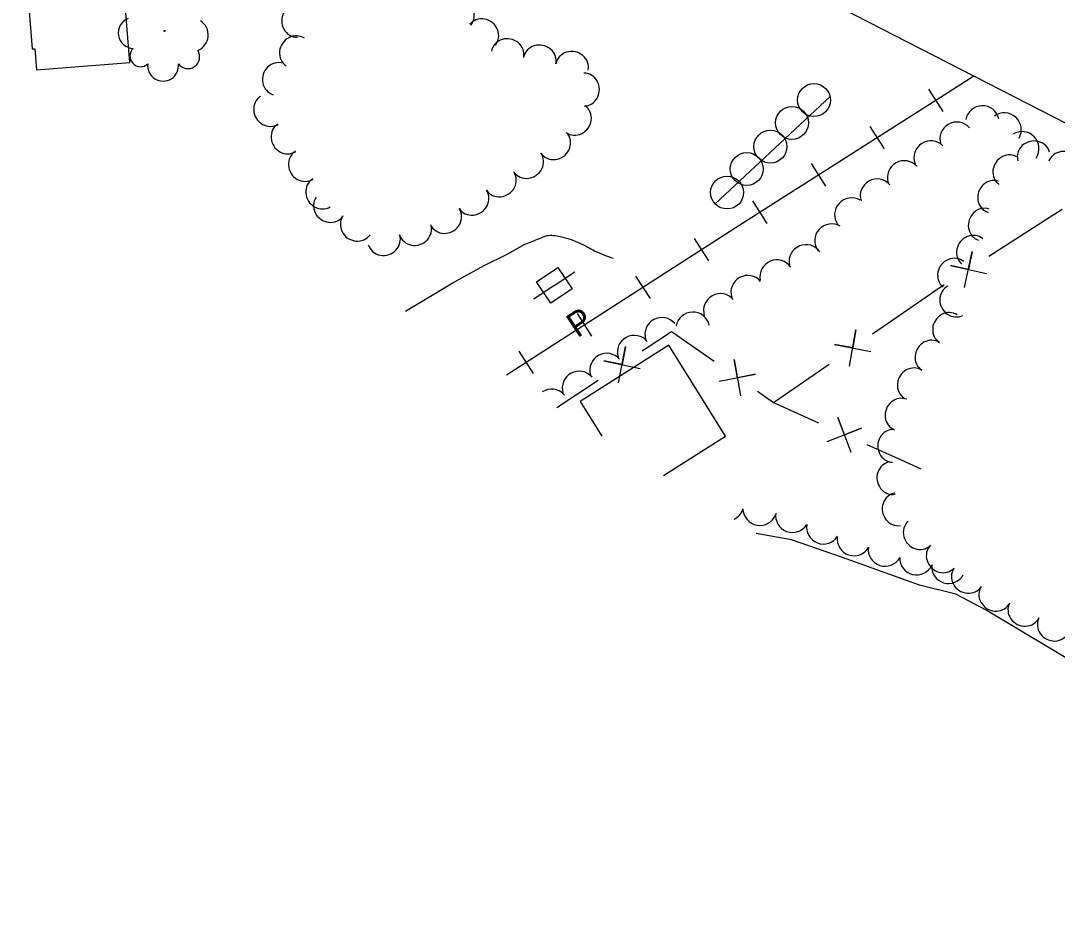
# Model space of a CAD drawing. Extents: x 1746010 to 1754829, y 655801 to 663091.
# Drawn here: x 1746597.6 to 1746912.4, y 662299.8 to 662573.6 of the extents above; entities that cross this region are included whole.
import ezdxf

# ---------------------------------------------------------------- set-up
doc = ezdxf.new("R2010")
doc.units = 0
for name, color, linetype in [('SURVEY - AERIAL SURVEY - Photo Control - Points - Elevations', 7, 'Continuous'), ('SURVEY - AERIAL SURVEY - Photo Control - Points - Locators', 7, 'Continuous'), ('SURVEY - AERIAL SURVEY - Photo Control with Text', 7, 'Continuous'), ('SURVEY - CENTERLINE - Existing Roads - Development', 7, 'Continuous'), ('SURVEY - CENTERLINE - Existing Roads Curve Text', 7, 'Continuous'), ('SURVEY - CENTERLINE - Existing Roads Text', 7, 'Continuous')]:
    doc.layers.add(name, color=color, linetype=linetype)

msp = doc.modelspace()

# ---------------------------------------------------------------- linework, layer by layer
at = {"layer": 'SURVEY - AERIAL SURVEY - Photo Control - Points - Elevations'}
msp.add_lwpolyline([(1746939.36, 662658.3), (1747047.15, 662601.95), (1746935.67, 662531.86), (1746826.79, 662587.8)], dxfattribs=at)
at = {"layer": 'SURVEY - AERIAL SURVEY - Photo Control - Points - Locators'}
for p, q in [((1746877.74, 662546.04), (1746873.38, 662552.86)), ((1746859.93, 662534.72), (1746855.57, 662541.54)), ((1746842.12, 662523.4), (1746837.77, 662530.22)), ((1746824.32, 662512.08), (1746819.96, 662518.9)), ((1746806.57, 662500.69), (1746802.18, 662507.5)), ((1746788.82, 662489.27), (1746784.44, 662496.08)), ((1746771.08, 662477.86), (1746766.69, 662484.66)), ((1746753.33, 662466.44), (1746748.95, 662473.25))]:
    msp.add_line(p, q, dxfattribs=at)
for points in [[(1746887.11, 662556.81), (1746879.12, 662551.72), (1746817.44, 662512.5), (1746745.08, 662465.95)], [(1746714.45, 662485.44), (1746728.61, 662493.92), (1746738.34, 662499.27), (1746745.47, 662502.86), (1746750.71, 662505.8)], [(1747021.09, 662299.79), (1747018.78, 662306.1), (1747009.96, 662317.06), (1746994.58, 662331.26), (1746981.41, 662340.35), (1746952.61, 662356.87), (1746930.16, 662371.03), (1746910.96, 662382.58), (1746890.81, 662394.58), (1746881.63, 662399.49), (1746870.54, 662402.23), (1746847.21, 662410.58), (1746831.64, 662415.93), (1746820.94, 662417.91)]]:
    msp.add_lwpolyline(points, dxfattribs=at)
msp.add_spline([(1746750.71, 662505.8), (1746755.1, 662507.49), (1746757.41, 662508.35), (1746761.43, 662508.07), (1746767.41, 662506.09), (1746771.87, 662503.74), (1746777.48, 662501.47)], degree=3, dxfattribs=at)
at = {"layer": 'SURVEY - AERIAL SURVEY - Photo Control with Text'}
for p, q in [((1746808.36, 662517.96), (1746843.47, 662550.64)), ((1746838.52, 662549.5), (1746838.52, 662549.5)), ((1746831.87, 662542.6), (1746831.87, 662542.6)), ((1746825.31, 662535.39), (1746825.31, 662535.39)), ((1746818.14, 662528.6), (1746818.14, 662528.6)), ((1746812.16, 662521.45), (1746812.16, 662521.45))]:
    msp.add_line(p, q, dxfattribs=at)
for centre in [(1746838.51, 662549.54), (1746831.83, 662542.6), (1746825.27, 662535.39), (1746818.1, 662528.6), (1746812.12, 662521.45)]:
    msp.add_circle(centre, 5, dxfattribs=at)
at = {"layer": 'SURVEY - CENTERLINE - Existing Roads - Development'}
for points in [[(1746602.38, 662558.69), (1746630.75, 662560.99), (1746627.8, 662597.33), (1746622.54, 662602.85), (1746608.66, 662601.72), (1746608.07, 662609.06), (1746597.57, 662608.21), (1746601.07, 662565.09), (1746601.86, 662565.15), (1746602.38, 662558.69)], [(1746901.24, 662508.29), (1746913.89, 662516.36)], [(1746891.63, 662502.15), (1746901.24, 662508.29)], [(1746884.23, 662492.56), (1746886.58, 662503.56), (1746885.45, 662498.09), (1746879.93, 662499.31), (1746890.89, 662496.81)], [(1746865.67, 662485.04), (1746875.48, 662491.84), (1746878.06, 662493.49)], [(1746856.3, 662478.54), (1746865.67, 662485.04)], [(1746786.34, 662473.35), (1746795.21, 662479.23), (1746795.83, 662478.8)], [(1746849.27, 662468.67), (1746851.2, 662479.75), (1746850.28, 662474.24), (1746844.71, 662475.25), (1746855.76, 662473.18)], [(1746795.83, 662478.8), (1746808.15, 662470.25)], [(1746779.1, 662463.63), (1746781.26, 662474.66), (1746780.22, 662469.17), (1746774.68, 662470.3), (1746785.69, 662468)], [(1746809.67, 662464.2), (1746820.73, 662466.27), (1746815.24, 662465.2), (1746814.24, 662470.77), (1746816.17, 662459.69)], [(1746830.75, 662460.82), (1746843.07, 662469.36)], [(1746760.42, 662456.16), (1746772.92, 662464.45)], [(1746821.38, 662461.07), (1746826.24, 662457.69), (1746830.75, 662460.82)], [(1746826.24, 662457.69), (1746839.91, 662451.53)], [(1746842.5, 662445.86), (1746852.99, 662449.91), (1746847.79, 662447.87), (1746845.79, 662453.16), (1746849.7, 662442.62)], [(1746854.57, 662444.92), (1746864.96, 662440.24)], [(1746864.96, 662440.24), (1746870.98, 662437.53)]]:
    msp.add_lwpolyline(points, dxfattribs=at)
at = {"layer": 'SURVEY - CENTERLINE - Existing Roads Curve Text'}
for q in [(1746765.87, 662497.4), (1746753.38, 662489.1)]:
    msp.add_line((1746759.62, 662493.25), q, dxfattribs=at)
msp.add_lwpolyline([(1746754.22, 662494.34), (1746760.71, 662498.66), (1746765.03, 662492.16), (1746758.53, 662487.84)], close=True, dxfattribs=at)
msp.add_lwpolyline([(1746792.82, 662435.47), (1746811.66, 662447.45), (1746794.38, 662475.04), (1746767.51, 662457.95), (1746774.11, 662447.42)], dxfattribs=at)
at = {"layer": 'SURVEY - CENTERLINE - Existing Roads Text'}
msp.add_circle((1746641.26, 662570.53), 0.164, dxfattribs=at)
for centre, radius, start, end in [((1746631.89, 662569.94), 4.7, 111.3897, 268.1786), ((1746649.47, 662569.33), 5.06, 291.4323, 58.2779), ((1746633.96, 662562.9), 3.23, 133.5059, 312.2515), ((1746648.34, 662562.65), 3.57, 216.1452, 33.4644), ((1746640.8, 662559.98), 4.69, 173.5266, 6.9462), ((1746889.66, 662542.69), 5.13, 12.9459, 169.7393), ((1746896.35, 662540.52), 5.13, 329.7073, 126.5007), ((1746881.89, 662537.73), 5.13, 41.859, 198.6525), ((1746901.72, 662534.83), 5.13, 325.6722, 122.4656), ((1746874.01, 662532.04), 5.13, 44.4925, 201.2859), ((1746865.93, 662525.99), 5.13, 40.7435, 197.5369), ((1746857.69, 662520.45), 5.13, 40.7435, 197.5369), ((1746849.91, 662514.71), 5.13, 59.3927, 216.1862), ((1746843.86, 662506.81), 5.13, 59.3927, 216.1862), ((1746836.09, 662500.49), 5.13, 34.4858, 191.2792), ((1746827.23, 662495.87), 5.13, 34.4858, 191.2792), ((1746818.41, 662491.14), 5.13, 40.538, 197.3314), ((1746810.1, 662485.61), 5.13, 40.538, 197.3314), ((1746792.29, 662478.36), 5.13, 40.0009, 196.7944), ((1746801.7, 662480.03), 5.13, 13.0642, 169.8577), ((1746783.92, 662472.93), 5.13, 40.0009, 196.7944), ((1746775.55, 662467.49), 5.13, 40.0009, 196.7944), ((1746767.18, 662462.05), 5.13, 40.0009, 196.7944), ((1746758.81, 662456.62), 5.13, 40.0009, 123.6128), ((1746812.07, 662426.88), 5.13, 294.7628, 344.3641), ((1746822.06, 662425.45), 5.13, 181.5927, 338.3862), ((1746831.99, 662423.31), 5.13, 171.3041, 328.0975), ((1746841.37, 662419.8), 5.13, 170.5653, 327.3587), ((1746850.66, 662416.25), 5.13, 172.8993, 329.6927), ((1746860.12, 662413.06), 5.13, 172.8993, 329.6927), ((1746869.66, 662410.44), 5.13, 177.9779, 334.7713), ((1746879.37, 662407.83), 5.13, 174.489, 331.2824)]:
    msp.add_arc(centre, radius, start, end, dxfattribs=at)
for centre, major_axis in [((1746730.43, 662575.51), (3.86, -3.18)), ((1746681.54, 662573.61), (-0.08, 5)), ((1746737.87, 662569.4), (3.86, -3.18)), ((1746680.97, 662564.14), (2.76, 4.17)), ((1746745.42, 662563.47), (4.91, -0.97)), ((1746755.22, 662561.53), (4.91, -0.97)), ((1746765.02, 662559.6), (4.91, -0.97)), ((1746675.7, 662555.93), (1.49, 4.77)), ((1746768.63, 662552.73), (0.04, -5)), ((1746673.1, 662546.45), (-2.67, 4.22)), ((1746766.1, 662543.75), (-2.92, -4.06)), ((1746678.38, 662538.11), (-2.67, 4.22)), ((1746759.69, 662536.25), (-4.1, -2.86)), ((1746905.24, 662532.41), (4.83, 1.28)), ((1746683.65, 662529.74), (-2.66, 4.23)), ((1746751.48, 662530.54), (-4.1, -2.86)), ((1746897.65, 662527.98), (2.86, 4.1)), ((1746914.49, 662529.17), (4.67, -1.8)), ((1746743.19, 662524.94), (-4.16, -2.78)), ((1746688.91, 662521.37), (-2.66, 4.23)), ((1746892.98, 662520.14), (1.61, 4.74)), ((1746691.38, 662517.18), (-4.11, 2.85)), ((1746734.87, 662519.39), (-4.16, -2.78)), ((1746890.12, 662511.69), (1.61, 4.74)), ((1746699.55, 662511.5), (-4.11, 2.85)), ((1746726.56, 662513.84), (-4.16, -2.78)), ((1746717.38, 662510.13), (-4.76, -1.54)), ((1746707.9, 662507.06), (-4.76, -1.54)), ((1746886.63, 662503.56), (3.18, 3.86)), ((1746880.89, 662496.6), (3.18, 3.86)), ((1746881.48, 662488.58), (-2.27, 4.45)), ((1746879.35, 662480.08), (2.69, 4.22)), ((1746873.99, 662471.67), (2.69, 4.22)), ((1746868.62, 662463.26), (2.69, 4.22)), ((1746864.85, 662454), (1.85, 4.64)), ((1746862.57, 662444.5), (0.17, 5)), ((1746862.34, 662434.72), (-0.84, 4.93)), ((1746863.95, 662425.25), (-0.84, 4.93)), ((1746870.46, 662417.88), (-3.39, 3.67)), ((1746877.48, 662410.83), (-3.6, 3.47)), ((1746885.16, 662404.53), (-4.19, 2.73)), ((1746893.51, 662399.08), (-4.19, 2.73)), ((1746902.37, 662394.49), (-4.47, 2.25)), ((1746911.3, 662389.99), (-4.47, 2.25))]:
    msp.add_ellipse(centre, major_axis=major_axis, ratio=0.940188, start_param=0, end_param=3.141593, dxfattribs=at)

# ---------------------------------------------------------------- texts
at = {"layer": 'SURVEY - CENTERLINE - Existing Roads Curve Text'}
msp.add_text('P', height=7.48, rotation=33.6177, dxfattribs=at).set_placement((1746766.62, 662477.12))

doc.saveas('drawing.dxf')
